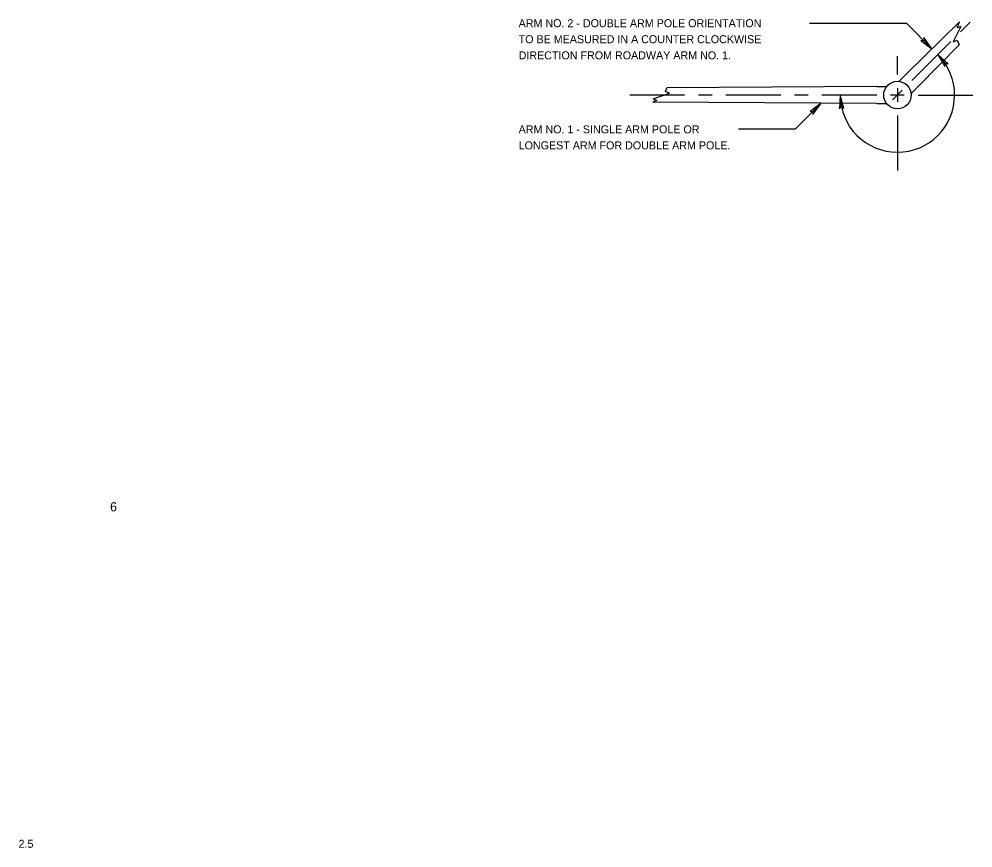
# Model space of a CAD drawing. Extents: x 2146427 to 2147986, y 2147023 to 2147568.
# Drawn here: x 2147569.5 to 2147986.4, y 2147022.5 to 2147384.8 of the extents above; entities that cross this region are included whole.
import ezdxf

# ---------------------------------------------------------------- set-up
doc = ezdxf.new("R2010")
doc.units = 0
doc.layers.add('50', color=7, linetype='Continuous')
doc.layers.add('TextShtNo', color=7, linetype='Continuous')

msp = doc.modelspace()

# ---------------------------------------------------------------- linework, layer by layer
at = {"layer": '50'}
for p, q in [((2147914.95, 2147382.96), (2147957.4, 2147382.96)), ((2147957.1, 2147360.63), (2147980.46, 2147383.67)), ((2147957.4, 2147382.96), (2147968.49, 2147371.87)), ((2147981.09, 2147381.58), (2147977.74, 2147374.88)), ((2147979.46, 2147381), (2147980.46, 2147383.67)), ((2147981.09, 2147381.58), (2147979.46, 2147381)), ((2147980.97, 2147379.19), (2147985.21, 2147383.43)), ((2147968.49, 2147371.87), (2147964.89, 2147376.74)), ((2147964.89, 2147376.74), (2147965.1, 2147375.26)), ((2147959.75, 2147357.98), (2147976.73, 2147374.95)), ((2147962.41, 2147355.33), (2147980.36, 2147373.53)), ((2147965.1, 2147375.26), (2147963.61, 2147375.47)), ((2147963.61, 2147375.47), (2147968.49, 2147371.87)), ((2147977.74, 2147374.88), (2147979.56, 2147375.55)), ((2147979.56, 2147375.55), (2147980.36, 2147373.53)), ((2147953.39, 2147360.61), (2147953.39, 2147368.65)), ((2147971.07, 2147369.29), (2147974.17, 2147364.07)), ((2147975.56, 2147365.21), (2147971.07, 2147369.29)), ((2147974.17, 2147364.07), (2147974.11, 2147365.57)), ((2147974.11, 2147365.57), (2147975.56, 2147365.21)), ((2147957.1, 2147360.63), (2147954.05, 2147357.58)), ((2147944.39, 2147355.36), (2147852.63, 2147354.74)), ((2147944.39, 2147355.36), (2147948.71, 2147355.36)), ((2147962.41, 2147355.33), (2147959.35, 2147352.27)), ((2147860.39, 2147351.61), (2147836.39, 2147351.61)), ((2147846.62, 2147350.01), (2147853.72, 2147352.38)), ((2147851.96, 2147353.19), (2147852.63, 2147354.74)), ((2147853.72, 2147352.38), (2147851.96, 2147353.19)), ((2147872.39, 2147351.61), (2147866.39, 2147351.61)), ((2147902.39, 2147351.61), (2147878.39, 2147351.61)), ((2147914.39, 2147351.61), (2147908.39, 2147351.61)), ((2147944.39, 2147351.61), (2147920.39, 2147351.61)), ((2147928.39, 2147351.61), (2147928.14, 2147345.55)), ((2147929.93, 2147345.74), (2147928.39, 2147351.61)), ((2147956.39, 2147351.61), (2147950.39, 2147351.61)), ((2147951.27, 2147349.49), (2147955.51, 2147353.73)), ((2147953.39, 2147354.61), (2147953.39, 2147348.61)), ((2147962.39, 2147351.61), (2147986.39, 2147351.61)), ((2147944.39, 2147347.86), (2147846.44, 2147348.53)), ((2147846.62, 2147350.01), (2147848.17, 2147349.27)), ((2147848.17, 2147349.27), (2147846.68, 2147348.59)), ((2147908.83, 2147336.77), (2147920.08, 2147348.03)), ((2147920.08, 2147348.03), (2147915.2, 2147344.42)), ((2147916.48, 2147343.15), (2147920.08, 2147348.03)), ((2147944.39, 2147347.86), (2147948.71, 2147347.86)), ((2147915.2, 2147344.42), (2147916.69, 2147344.63)), ((2147916.69, 2147344.63), (2147916.48, 2147343.15)), ((2147928.14, 2147345.55), (2147928.9, 2147346.84)), ((2147928.9, 2147346.84), (2147929.93, 2147345.74)), ((2147953.39, 2147342.61), (2147953.39, 2147318.61)), ((2147883.97, 2147336.77), (2147908.83, 2147336.77))]:
    msp.add_line(p, q, dxfattribs=at)
msp.add_circle((2147953.39, 2147351.61), 6, dxfattribs=at)
for start, end in [(0, 45), (180, 0)]:
    msp.add_arc((2147953.39, 2147351.61), 25, start, end, dxfattribs=at)

# ---------------------------------------------------------------- texts
for s, height, p in [('ARM NO. 2 - DOUBLE ARM POLE ORIENTATION', 3.5001, (2147787.82, 2147381.26)), ('TO BE MEASURED IN A COUNTER CLOCKWISE', 3.5001, (2147787.82, 2147374.26)), ('DIRECTION FROM ROADWAY ARM NO. 1.', 3.5001, (2147787.82, 2147367.21)), ('ARM NO. 1 - SINGLE ARM POLE OR', 3.5001, (2147787.82, 2147334.86)), ('LONGEST ARM FOR DOUBLE ARM POLE.', 3.5001, (2147787.82, 2147327.86)), ('2.5', 3.5, (2147569.22, 2147022.58))]:
    msp.add_text(s, height=height, dxfattribs=at).set_placement(p)
at = {"layer": 'TextShtNo'}
msp.add_text('6', height=4, dxfattribs=at).set_placement((2147609.26, 2147169.63))

doc.saveas('drawing.dxf')
